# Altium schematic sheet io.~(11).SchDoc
size Letter
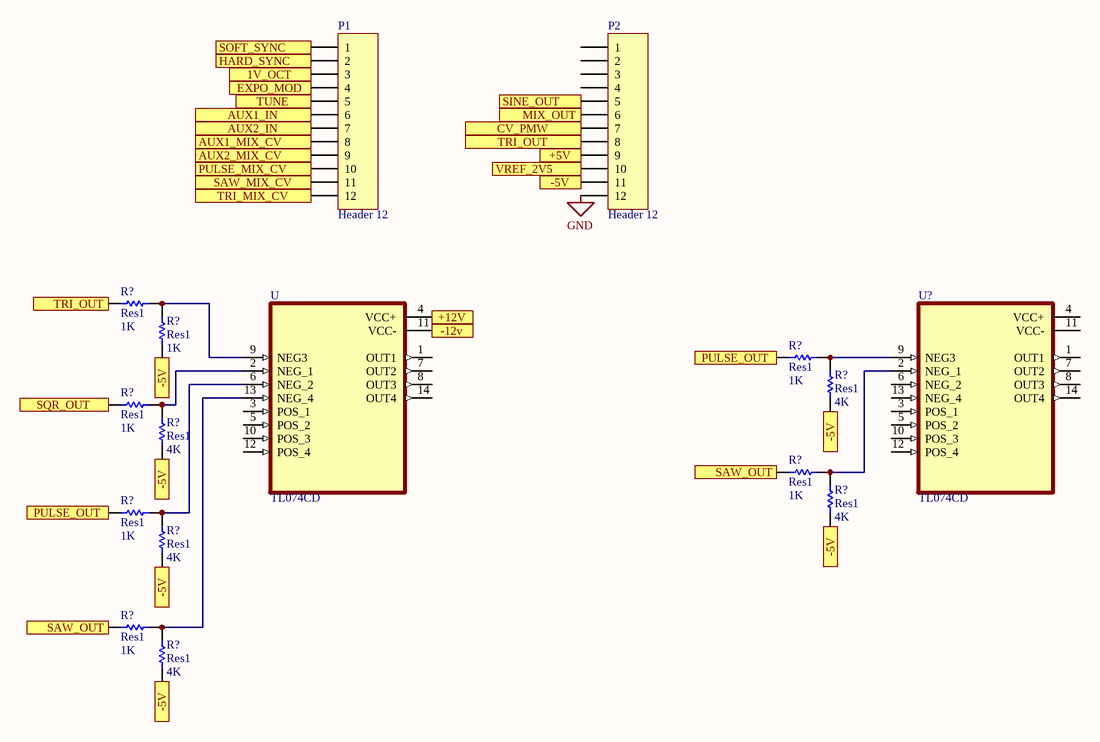
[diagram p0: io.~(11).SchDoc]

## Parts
(Parts that share a designator on the sheet are numbered #1, #2 ... from top to bottom, then left to right.)
P1  Header 12  [HDR1X12]
P2  Header 12  [HDR1X12]
R?#1  Res1  value 1K  [AXIAL-0.3]
R?#2  Res1  value 1K  [AXIAL-0.3]
R?#3  Res1  value 1K  [AXIAL-0.3]
R?#4  Res1  value 1K  [AXIAL-0.3]
R?#5  Res1  value 4K  [AXIAL-0.3]
R?#6  Res1  value 4K  [AXIAL-0.3]
R?#7  Res1  value 1K  [AXIAL-0.3]
R?#8  Res1  value 1K  [AXIAL-0.3]
R?#9  Res1  value 4K  [AXIAL-0.3]
R?#10  Res1  value 4K  [AXIAL-0.3]
R?#11  Res1  value 1K  [AXIAL-0.3]
R?#12  Res1  value 4K  [AXIAL-0.3]
U  TL074CD  [SOIC127P600X175-14N]
U?  TL074CD  [SOIC127P600X175-14N]

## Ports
1V_OCT, +5V, +12V, -5V, -12v, AUX1_IN, AUX1_MIX_CV, AUX2_IN, AUX2_MIX_CV, CV_PMW, EXPO_MOD, HARD_SYNC, MIX_OUT, PULSE_MIX_CV, PULSE_OUT, SAW_MIX_CV, SAW_OUT, SINE_OUT, SOFT_SYNC, SQR_OUT, TRI_MIX_CV, TRI_OUT, TUNE, VREF_2V5

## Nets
GND: P2.12
1V_OCT: P1.3 ; port 1V_OCT
+5V: P2.9 ; port +5V
+12V: U.4(VCC+) ; port +12V
-5V: P2.11 R?#2.1 R?#5.1 R?#6.1 R?#9.1 R?#10.1 R?#12.1 ; port -5V
-12v: U.11(VCC-) ; port -12v
AUX1_IN: P1.6 ; port AUX1_IN
AUX1_MIX_CV: P1.8 ; port AUX1_MIX_CV
AUX2_IN: P1.7 ; port AUX2_IN
AUX2_MIX_CV: P1.9 ; port AUX2_MIX_CV
CV_PMW: P2.7 ; port CV_PMW
EXPO_MOD: P1.4 ; port EXPO_MOD
HARD_SYNC: P1.2 ; port HARD_SYNC
MIX_OUT: P2.6 ; port MIX_OUT
PULSE_MIX_CV: P1.10 ; port PULSE_MIX_CV
PULSE_OUT: R?#3.1 R?#8.1 ; port PULSE_OUT
SAW_MIX_CV: P1.11 ; port SAW_MIX_CV
SAW_OUT: R?#7.1 R?#11.1 ; port SAW_OUT
SINE_OUT: P2.5 ; port SINE_OUT
SOFT_SYNC: P1.1 ; port SOFT_SYNC
SQR_OUT: R?#4.1 ; port SQR_OUT
TRI_MIX_CV: P1.12 ; port TRI_MIX_CV
TRI_OUT: P2.8 R?#1.1 ; port TRI_OUT
TUNE: P1.5 ; port TUNE
VREF_2V5: P2.10 ; port VREF_2V5
NetR?#1_2: R?#1.2 R?#2.2 U.9(NEG3)
NetR?#3_2: R?#3.2 R?#5.2 U?.9(NEG3)
NetR?#4_2: R?#4.2 R?#6.2 U.2(NEG_1)
NetR?#7_2: R?#7.2 R?#9.2 U?.2(NEG_1)
NetR?#8_2: R?#8.2 R?#10.2 U.6(NEG_2)
NetR?#11_2: R?#11.2 R?#12.2 U.13(NEG_4)

Not connected (* = marked no-connect by the designer): P2 1 2 3 4; U 1(OUT1) 3(POS_1) 5(POS_2) 7(OUT2) 8(OUT3) 10(POS_3) 12(POS_4) 14(OUT4); U? 1(OUT1) 3(POS_1) 4(VCC+) 5(POS_2) 6(NEG_2) 7(OUT2) 8(OUT3) 10(POS_3) 11(VCC-) 12(POS_4) 13(NEG_4) 14(OUT4)

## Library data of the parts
P1 P2 = Header 12: Header, 12-Pin
R?#1-R?#12 = Res1: Resistor
U U? = TL074CD: Quad Low-Noise JFET-Input General-Purpose Operational Amplifier 14-SOIC 0 to 70; MF: Texas Instruments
